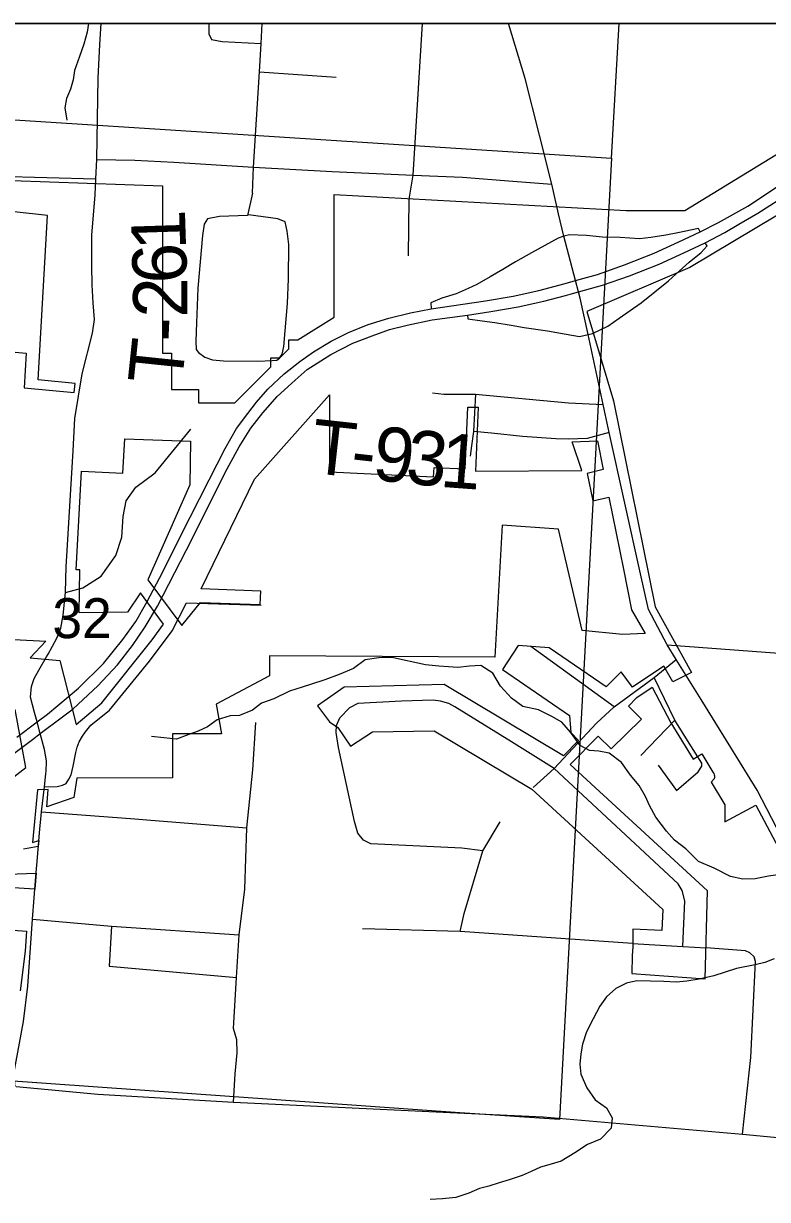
# Model space of a CAD drawing. Extents: x 0 to 34, y 0 to 22.
# Drawn here: x 6.529 to 7.308, y 19.668 to 20.9 of the extents above; entities that cross this region are included whole.
import ezdxf

# ---------------------------------------------------------------- set-up
doc = ezdxf.new("R2010")
doc.units = 0
for name, color, linetype in [('GM_X_City_Street', 7, 'Continuous'), ('GM_X_Corporation', 7, 'Continuous'), ('GM_X_Interchange_Ramps', 7, 'Continuous'), ('GM_X_Minor_River', 7, 'Continuous'), ('GM_X_Section_Text', 7, 'Continuous'), ('GM_X_State_Route', 7, 'Continuous'), ('GM_X_Township_Road', 7, 'Continuous'), ('GM_X_Township_Road_Text', 7, 'Continuous'), ('SH_Data', 7, 'Continuous')]:
    doc.layers.add(name, color=color, linetype=linetype)

msp = doc.modelspace()

# ---------------------------------------------------------------- linework, layer by layer
at = {"layer": 'GM_X_City_Street'}
for p, q in [((6.7759, 20.8495), (6.8565, 20.8439)), ((6.6997, 20.2932), (6.7779, 20.2908)), ((7.1479, 20.1841), (7.0605, 20.2475))]:
    msp.add_line(p, q, dxfattribs=at)
for points in [[(6.6046, 20.7373), (6.6054, 20.7575), (6.6068, 20.8428), (6.6087, 20.8781), (6.6101, 20.9)], [(6.723, 20.8992), (6.723, 20.8891), (6.7257, 20.8834), (6.737, 20.8812), (6.7778, 20.8792)], [(6.7688, 20.7224), (6.7699, 20.7494), (6.7759, 20.8495), (6.7778, 20.8792), (6.7789, 20.9)], [(6.933, 20.7161), (6.9371, 20.741), (6.947, 20.9)], [(6.4277, 20.812), (6.4393, 20.8101), (6.4742, 20.8054), (6.4775, 20.8049), (6.4808, 20.8034), (6.4838, 20.8015), (6.487, 20.7985), (6.4887, 20.7969), (6.4895, 20.7953), (6.4885, 20.7729), (6.4887, 20.7517), (6.4896, 20.7457), (6.4906, 20.743), (6.4921, 20.7414), (6.5016, 20.7401), (6.6046, 20.7373)], [(6.6054, 20.7575), (6.6454, 20.7569), (6.6862, 20.7546), (6.7699, 20.7494), (6.8522, 20.7451), (6.9371, 20.741), (6.9888, 20.7392), (7.0415, 20.7347), (7.0823, 20.7317)], [(6.7688, 20.7224), (6.7636, 20.6989), (6.7343, 20.6977), (6.7215, 20.6955), (6.718, 20.6898), (6.7162, 20.6778), (6.7115, 20.6229), (6.71, 20.5865), (6.7092, 20.5671), (6.7096, 20.5587), (6.712, 20.5555), (6.7189, 20.5504), (6.7268, 20.5476), (6.7385, 20.5467), (6.7742, 20.5462), (6.7895, 20.547), (6.7943, 20.5473), (6.797, 20.5495), (6.7998, 20.5537), (6.8017, 20.5616), (6.8054, 20.6066), (6.8063, 20.6327), (6.8068, 20.6685), (6.8049, 20.6824), (6.8031, 20.6924), (6.7952, 20.6954), (6.7644, 20.6996)], [(6.5726, 20.3041), (6.591, 20.309), (6.61, 20.3212), (6.6254, 20.3429), (6.6318, 20.362), (6.6331, 20.3837), (6.6364, 20.4), (6.6463, 20.4143), (6.6666, 20.4295), (6.704, 20.4751)], [(7.2032, 20.2492), (7.3486, 20.2383), (7.3732, 20.236), (7.4471, 20.2305), (7.5486, 20.221)], [(7.063, 20.0996), (7.0848, 20.1195), (7.1294, 20.167), (7.1479, 20.1841), (7.1896, 20.215), (7.2128, 20.2339)], [(7.2197, 19.9331), (7.2217, 19.9812), (7.219, 19.9918), (7.2147, 19.9989), (7.0848, 20.1195), (7.0401, 20.1475), (6.9808, 20.1844), (6.9744, 20.1879), (6.9659, 20.19), (6.958, 20.1911), (6.925, 20.19), (6.8791, 20.1876), (6.8704, 20.1832), (6.8602, 20.1728)], [(7.1671, 19.9362), (7.2197, 19.9331), (7.2442, 19.9317)]]:
    msp.add_lwpolyline(points, dxfattribs=at)
at = {"layer": 'GM_X_Corporation'}
for points in [[(6.4765, 20.737), (6.6744, 20.73), (6.6744, 20.5546), (6.6838, 20.5546), (6.6838, 20.5167), (6.7122, 20.5167), (6.7122, 20.5025), (6.7501, 20.5025), (6.788, 20.5403), (6.788, 20.5498), (6.7975, 20.5498), (6.8069, 20.5593), (6.8069, 20.5688), (6.8164, 20.5688), (6.8543, 20.5924), (6.8543, 20.7208), (7.1602, 20.7043), (7.2218, 20.7043), (7.5423, 20.9), (5.1364, 20.9)], [(7.501, 20.8077), (7.2272, 20.6445), (7.1191, 20.5983), (7.147, 20.5046), (7.1908, 20.289), (7.2288, 20.2203), (7.2094, 20.2104), (7.2, 20.2267), (7.1669, 20.205), (7.1552, 20.2209), (7.1394, 20.2052), (7.0796, 20.2459), (7.0473, 20.2484), (7.0308, 20.2233), (7.1009, 20.1752), (7.1022, 20.1574), (7.1104, 20.149), (7.0946, 20.1328), (6.9696, 20.2075), (6.8648, 20.2047), (6.8367, 20.1852), (6.8496, 20.1686), (6.858, 20.1626), (6.8716, 20.1431), (6.8944, 20.1579), (6.9591, 20.1592), (7.0615, 20.098), (7.1987, 19.972), (7.1977, 19.9498), (7.1673, 19.9515), (7.1672, 19.9329), (7.1667, 19.9236), (7.1662, 19.9048), (7.2431, 19.8994), (7.2455, 19.9914), (7.1016, 20.1237), (7.1311, 20.1536), (7.1447, 20.1403), (7.1763, 20.1713), (7.1628, 20.1849), (7.1714, 20.1939), (7.1875, 20.2047), (7.2072, 20.1675), (7.2307, 20.1295), (7.2397, 20.1351), (7.2513, 20.1158), (7.2521, 20.1145), (7.2526, 20.1131), (7.2529, 20.1119), (7.2528, 20.1104), (7.2525, 20.1087), (7.2493, 20.1053), (7.2636, 20.0815), (7.2638, 20.0638), (7.2961, 20.0811), (7.3375, 20.0037)], [(6.3355, 20.5726), (6.5315, 20.5547), (6.5294, 20.5184), (6.5818, 20.5136), (6.5827, 20.523), (6.544, 20.5266), (6.5538, 20.699), (6.4551, 20.7098)], [(6.2227, 20.2703), (6.552, 20.253), (6.5357, 20.2356), (6.5667, 20.2326), (6.584, 20.1656), (6.6109, 20.1884), (6.6634, 20.2544), (6.6756, 20.2707), (6.6512, 20.3036), (6.6377, 20.2835), (6.5871, 20.2827), (6.5877, 20.3277), (6.5839, 20.3277), (6.5894, 20.4311), (6.6329, 20.4289), (6.6348, 20.4648), (6.7038, 20.4626), (6.7029, 20.4169), (6.659, 20.3173), (6.6945, 20.2694), (6.7143, 20.2935), (6.7769, 20.2913), (6.7774, 20.3055), (6.7148, 20.3077), (6.7708, 20.4226), (6.8494, 20.5112), (6.8494, 20.4304), (6.9585, 20.4251), (6.9592, 20.4348), (6.9915, 20.4337), (6.9944, 20.4982), (7.0053, 20.4982), (7.0025, 20.431), (7.114, 20.4317), (7.1038, 20.4618), (7.1302, 20.4627), (7.1363, 20.433), (7.1195, 20.4288), (7.1253, 20.4), (7.1421, 20.404), (7.1575, 20.3284), (7.1661, 20.286), (7.1803, 20.2612), (7.1564, 20.2599), (7.1144, 20.2643), (7.0894, 20.3702), (7.0304, 20.3746), (7.0227, 20.2361), (6.7864, 20.2377), (6.7864, 20.2166), (6.7307, 20.187), (6.7361, 20.1561), (6.6848, 20.1559), (6.685, 20.1097), (6.5846, 20.1094), (6.5814, 20.0893), (6.5531, 20.0795), (6.5547, 20.0976), (6.5434, 20.0973), (6.5382, 20.0423), (6.5447, 20.0443), (6.5442, 20.0378), (6.5286, 20.0351)], [(6.389, 20.0105), (6.5312, 20.1207), (6.5201, 20.1813)], [(6.5118, 20.009), (6.5419, 20.0099), (6.5405, 19.9931), (6.5071, 19.9954)], [(6.4943, 19.9519), (6.532, 19.9492), (6.5306, 19.9284), (6.5253, 19.8869)]]:
    msp.add_lwpolyline(points, dxfattribs=at)
for points in [[(7.1529, 20.9), (6.106, 20.9), (6.1004, 20.8259), (7.1451, 20.7589)], [(6.1004, 20.8259), (7.1451, 20.7589), (7.0904, 19.7521), (6.9862, 19.7588), (6.0298, 19.8267)]]:
    msp.add_lwpolyline(points, close=True, dxfattribs=at)
at = {"layer": 'GM_X_Interchange_Ramps'}
msp.add_line((7.1204, 20.5743), (7.1252, 20.5753), dxfattribs=at)
for points in [[(7.238, 20.6817), (7.2363, 20.6853), (7.2145, 20.6809), (7.202, 20.6783), (7.1861, 20.676), (7.1742, 20.6746), (7.1539, 20.6757), (7.1354, 20.6762), (7.1189, 20.6781), (7.1011, 20.6786), (7.095, 20.6771)], [(7.095, 20.6771), (7.0891, 20.6752), (7.0611, 20.6599), (7.0442, 20.6505), (7.031, 20.6422), (7.0179, 20.6345), (7.0038, 20.6268), (6.9948, 20.6223), (6.9821, 20.6169), (6.967, 20.6123), (6.9557, 20.6075), (6.9561, 20.6011)], [(7.2124, 20.6374), (7.2264, 20.6499), (7.2389, 20.6603), (7.2452, 20.6673), (7.2433, 20.6704)], [(7.1252, 20.5753), (7.1411, 20.5831), (7.1531, 20.5912), (7.176, 20.6073), (7.2047, 20.6304), (7.2124, 20.6374)], [(6.9942, 20.5946), (6.9943, 20.5907), (7.0095, 20.5884), (7.0227, 20.5868), (7.0397, 20.5842), (7.0536, 20.5817), (7.078, 20.578), (7.0973, 20.5746), (7.1113, 20.5721), (7.1204, 20.5743)]]:
    msp.add_lwpolyline(points, dxfattribs=at)
at = {"layer": 'GM_X_Minor_River'}
for points in [[(6.5967, 20.9), (6.5954, 20.891), (6.5919, 20.8782), (6.5873, 20.8653), (6.5823, 20.8509), (6.5807, 20.8411), (6.578, 20.8312), (6.5737, 20.8214), (6.5722, 20.8116), (6.574, 20.7986)], [(7.2525, 20.0151), (7.2362, 20.0224), (7.223, 20.0354), (7.211, 20.0446), (7.2027, 20.0541), (7.1915, 20.0686), (7.1847, 20.0808), (7.1806, 20.0903), (7.1739, 20.1017), (7.1649, 20.1128), (7.1555, 20.1258), (7.1427, 20.1357), (7.1318, 20.1377), (7.1219, 20.1385), (7.1121, 20.1439), (7.102, 20.1576), (7.093, 20.1683), (7.0824, 20.174), (7.0685, 20.181), (7.0522, 20.1845), (7.0402, 20.1933), (7.0286, 20.2059), (7.0207, 20.2196), (7.0079, 20.2276), (6.9962, 20.227), (6.984, 20.2255), (6.9742, 20.2263), (6.964, 20.2268), (6.95, 20.2284), (6.939, 20.2307), (6.9258, 20.2335), (6.9152, 20.2358), (6.9012, 20.2356), (6.8868, 20.2334), (6.8747, 20.2244), (6.8595, 20.218), (6.8447, 20.2124), (6.8307, 20.208), (6.8208, 20.205), (6.8075, 20.2005), (6.7912, 20.1927), (6.7783, 20.1882), (6.7688, 20.1807), (6.7551, 20.1751), (6.7453, 20.1748), (6.7316, 20.1707), (6.7214, 20.1632), (6.7119, 20.1587), (6.702, 20.1553), (6.6891, 20.1505), (6.6759, 20.1517), (6.663, 20.1533)], [(7.3579, 19.9415), (7.3528, 19.9497), (7.3464, 19.9593), (7.3442, 19.9718), (7.3378, 19.987), (7.3307, 19.9987), (7.3193, 20.0083), (7.3095, 20.0068), (7.2955, 20.0042), (7.2826, 20.0038), (7.2698, 20.0065), (7.2525, 20.0151)], [(7.3153, 19.9203), (7.3058, 19.9165), (7.2956, 19.9139), (7.2759, 19.9102), (7.2523, 19.9025)], [(7.2523, 19.9025), (7.2369, 19.8988), (7.224, 19.897), (7.2126, 19.8959), (7.1998, 19.8964), (7.1858, 19.8969), (7.1714, 19.8973), (7.1608, 19.8948), (7.1494, 19.8891), (7.1399, 19.8805), (7.1326, 19.8707), (7.1257, 19.8574), (7.1188, 19.8438), (7.1145, 19.831), (7.113, 19.8207), (7.1118, 19.8101), (7.1128, 19.7995), (7.1191, 19.785), (7.1278, 19.7725), (7.1398, 19.7641), (7.1458, 19.7538), (7.1446, 19.7428), (7.1335, 19.7315), (7.1199, 19.7259), (7.1066, 19.7169), (7.0921, 19.7082), (7.0819, 19.7053), (7.0705, 19.7019), (7.0607, 19.6975), (7.0512, 19.6933), (7.0379, 19.6889), (7.0273, 19.6855), (7.0163, 19.6822), (7.0068, 19.6796), (6.9954, 19.6748), (6.9818, 19.6703), (6.9678, 19.6689), (6.9549, 19.6682)]]:
    msp.add_lwpolyline(points, dxfattribs=at)
at = {"layer": 'GM_X_State_Route'}
for p, q in [((7.0896, 20.7005), (7.0841, 20.7239)), ((7.1754, 20.3237), (7.1425, 20.4715)), ((6.5462, 20.1562), (6.5696, 20.1738)), ((6.5381, 20.1501), (6.5462, 20.1562))]:
    msp.add_line(p, q, dxfattribs=at)
for points in [[(7.0695, 20.783), (7.0545, 20.8424), (7.0369, 20.9)], [(7.2785, 20.6898), (7.2982, 20.7015), (7.3321, 20.723), (7.3682, 20.7474), (7.4055, 20.7724), (7.443, 20.7974), (7.5175, 20.8456), (7.5911, 20.8953), (7.5981, 20.9)], [(7.0841, 20.7239), (7.0823, 20.7317), (7.0695, 20.783)], [(6.5219, 20.1524), (6.5429, 20.1684), (6.5538, 20.1766), (6.5865, 20.2039), (6.6125, 20.2296), (6.6329, 20.2549), (6.6464, 20.2737), (6.6579, 20.2938), (6.6747, 20.3255), (6.6933, 20.363), (6.7232, 20.4221), (6.7401, 20.455), (6.7521, 20.4757), (6.7638, 20.4916), (6.7729, 20.5032), (6.7849, 20.517), (6.8018, 20.5331), (6.8183, 20.5461), (6.8326, 20.5561), (6.851, 20.5671), (6.8694, 20.5764), (6.89, 20.5847), (6.9115, 20.5915), (6.9344, 20.5971), (6.9561, 20.6011), (7.0131, 20.6095), (7.0418, 20.6144), (7.0689, 20.6205), (7.0964, 20.6277), (7.1074, 20.6307), (7.1304, 20.6371), (7.1586, 20.6471), (7.1898, 20.6593), (7.2156, 20.6712), (7.238, 20.6817), (7.2571, 20.6916), (7.2878, 20.7088), (7.3254, 20.7336)], [(7.112, 20.6122), (7.1105, 20.6189), (7.1074, 20.6307), (7.095, 20.6771), (7.0896, 20.7005)], [(7.2433, 20.6704), (7.2639, 20.6811), (7.2785, 20.6898)], [(7.0966, 20.6151), (7.1017, 20.6164), (7.1105, 20.6189), (7.1357, 20.6258), (7.1639, 20.6358), (7.1951, 20.648), (7.2209, 20.6599), (7.2433, 20.6704)], [(6.9942, 20.5946), (7.0184, 20.5982), (7.0471, 20.6031), (7.0742, 20.6092), (7.0966, 20.6151)], [(7.1425, 20.4715), (7.1362, 20.5011), (7.1204, 20.5743), (7.112, 20.6122)], [(6.8133, 20.5263), (6.826, 20.5375), (6.8507, 20.5534), (6.8738, 20.5653), (6.8941, 20.573), (6.9122, 20.5794), (6.9308, 20.584), (6.9569, 20.5896), (6.9942, 20.5946)], [(6.5696, 20.1738), (6.5806, 20.182), (6.6067, 20.2062), (6.6271, 20.2281), (6.6429, 20.2486), (6.6562, 20.268), (6.6692, 20.2896), (6.6993, 20.3481), (6.7421, 20.4334), (6.7549, 20.4567), (6.7669, 20.4763), (6.7794, 20.4921), (6.7947, 20.5094), (6.8095, 20.523), (6.8133, 20.5263)], [(7.2389, 20.192), (7.2128, 20.2339), (7.2032, 20.2492), (7.1837, 20.2863), (7.1754, 20.3237)], [(7.351, 19.9942), (7.3282, 20.0384), (7.2977, 20.0968), (7.2702, 20.1418), (7.2389, 20.192)], [(6.4977, 20.12), (6.5228, 20.1384), (6.5381, 20.1501)]]:
    msp.add_lwpolyline(points, dxfattribs=at)
at = {"layer": 'GM_X_Township_Road'}
for p, q in [((6.9322, 20.6566), (6.933, 20.7161)), ((7.1758, 20.1332), (7.2112, 20.1703)), ((6.5523, 20.1168), (6.5528, 20.1266)), ((7.194, 20.1232), (7.2132, 20.0967)), ((6.546, 20.0564), (6.5468, 20.0664)), ((6.5475, 20.0744), (6.6453, 20.0668)), ((6.5435, 20.0265), (6.546, 20.0564)), ((6.5418, 20.0066), (6.5435, 20.0265))]:
    msp.add_line(p, q, dxfattribs=at)
for points in [[(6.5739, 20.3363), (6.5806, 20.4523), (6.5825, 20.4861), (6.5901, 20.5329), (6.6012, 20.5757), (6.603, 20.5898), (6.6016, 20.6074), (6.6007, 20.6262), (6.6002, 20.6461), (6.6002, 20.6618), (6.6004, 20.6783), (6.604, 20.7204), (6.6046, 20.7373)], [(6.9575, 20.5131), (6.9691, 20.5118), (7.0025, 20.5118), (7.0999, 20.5025), (7.1362, 20.5011)], [(7.0025, 20.5118), (7.0003, 20.4726), (6.9983, 20.4575), (6.997, 20.4469)], [(7.1425, 20.4715), (7.1194, 20.4654), (7.0998, 20.4646), (7.0866, 20.4651), (7.0517, 20.4674), (7.0192, 20.471), (7.0003, 20.4726)], [(6.5529, 20.2365), (6.5545, 20.2393), (6.5637, 20.256), (6.5678, 20.2667), (6.5703, 20.2802), (6.5726, 20.3041), (6.5736, 20.3312), (6.5739, 20.3363)], [(6.5507, 20.1003), (6.5641, 20.1008), (6.5696, 20.1021), (6.5736, 20.1041), (6.5763, 20.1084), (6.5787, 20.1129), (6.5806, 20.1222), (6.5835, 20.1365), (6.585, 20.1421), (6.5871, 20.1477), (6.5905, 20.1535), (6.5937, 20.1579), (6.5992, 20.1649), (6.6188, 20.1809), (6.6607, 20.2319), (6.6847, 20.264), (6.6997, 20.2932)], [(6.5528, 20.1266), (6.5528, 20.1276), (6.5507, 20.1394), (6.5462, 20.1562), (6.5429, 20.1684), (6.5402, 20.1784), (6.5361, 20.1944), (6.5372, 20.2054), (6.54, 20.2138), (6.5448, 20.2226), (6.5529, 20.2365)], [(7.2264, 20.1461), (7.2112, 20.1703), (7.1896, 20.215)], [(6.7488, 19.8474), (6.7518, 19.9006), (6.7548, 19.9454), (6.7608, 19.9934), (6.7627, 20.0576), (6.7692, 20.1184), (6.7722, 20.168)], [(7.0103, 20.0333), (6.9881, 20.0362), (6.8929, 20.0406), (6.885, 20.0444), (6.8791, 20.052), (6.8756, 20.064), (6.8587, 20.1417), (6.8563, 20.1572), (6.8569, 20.1648), (6.8602, 20.1728)], [(7.2132, 20.0967), (7.2359, 20.1161), (7.2398, 20.122), (7.2395, 20.1253), (7.2264, 20.1461)], [(6.5468, 20.0664), (6.5475, 20.0744), (6.5507, 20.1003), (6.5521, 20.1139), (6.5523, 20.1168)], [(6.6453, 20.0668), (6.662, 20.0655), (6.7627, 20.0576)], [(6.9864, 19.9489), (6.9907, 19.9678), (7.0103, 20.0333), (7.0284, 20.0637)], [(6.5199, 19.7865), (6.5185, 19.7999), (6.5286, 19.8546), (6.5333, 19.8918), (6.5381, 19.9618), (6.5418, 20.0066)], [(6.5381, 19.9618), (6.6211, 19.9544), (6.7548, 19.9454)], [(6.6211, 19.9544), (6.6184, 19.9126), (6.7518, 19.9006)], [(7.1671, 19.9362), (6.9864, 19.9489), (6.8841, 19.9517)], [(7.2824, 19.7367), (7.2911, 19.817), (7.2958, 19.9174), (7.2944, 19.9225), (7.29, 19.9265), (7.2855, 19.9287), (7.2442, 19.9317)], [(6.7488, 19.7702), (6.7506, 19.7998), (6.7525, 19.8219), (6.7523, 19.8353), (6.7488, 19.8474)], [(6.5209, 19.7864), (6.6067, 19.7786), (6.7488, 19.7702), (6.9834, 19.759), (7.0732, 19.7546), (7.2824, 19.7367), (7.33, 19.7319), (7.4965, 19.7186)]]:
    msp.add_lwpolyline(points, dxfattribs=at)
at = {"layer": 'SH_Data'}
msp.add_line((2.1, 20.9), (8.9, 20.9), dxfattribs=at)

# ---------------------------------------------------------------- texts
at = {"layer": 'GM_X_Section_Text'}
msp.add_text('32', height=0.04186, rotation=0, dxfattribs=at).set_placement((6.559, 20.2562))
at = {"layer": 'GM_X_Township_Road_Text'}
for s, rotation, p in [('1', 91.831, (6.6992, 20.6633)), ('6', 91.8338, (6.7003, 20.6286)), ('2', 90.0162, (6.7004, 20.5919)), ('-', 87.221, (6.6992, 20.5658)), ('T', 84.0275, (6.6945, 20.5201)), ('T', 353.6868, (6.8279, 20.4296)), ('9', 353.6868, (6.8931, 20.4224)), ('3', 354.0744, (6.928, 20.4186)), ('1', 355.7358, (6.9643, 20.4148)), ('-', 353.6868, (6.8701, 20.425))]:
    msp.add_text(s, height=0.0568, rotation=rotation, dxfattribs=at).set_placement(p)

doc.saveas('drawing.dxf')
